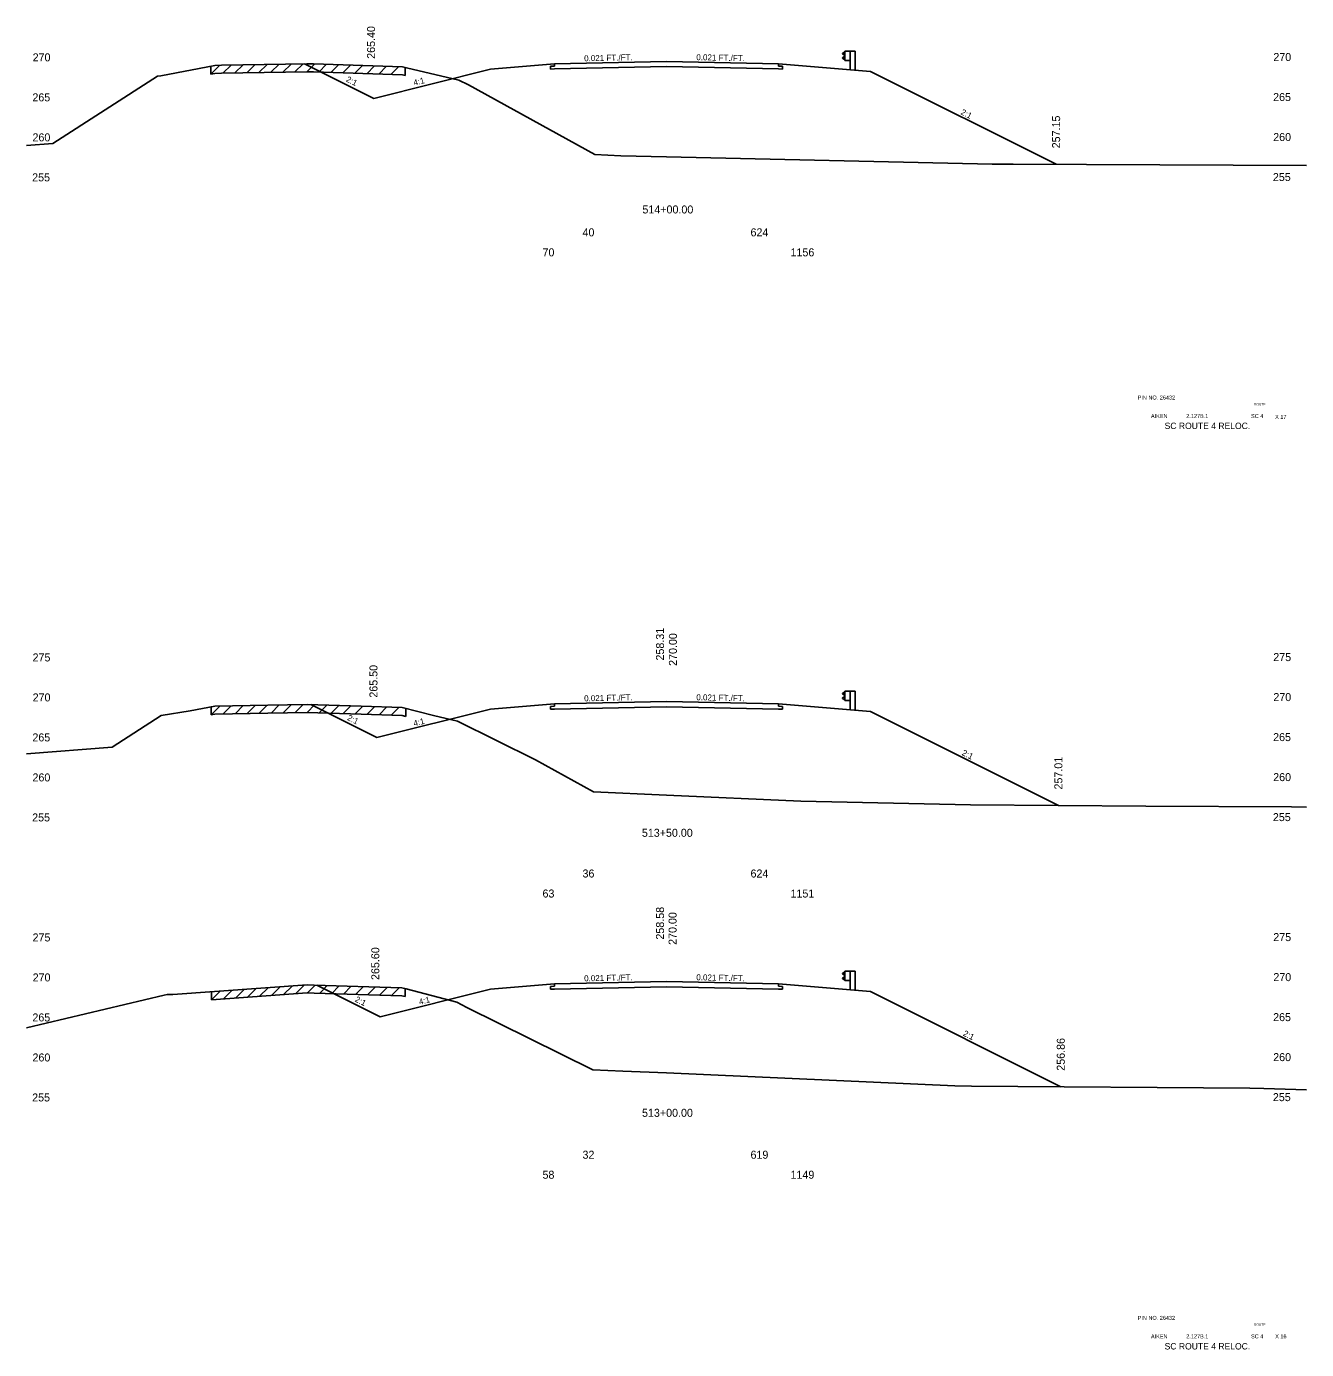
# Model space of a CAD drawing. Extents: x 2967 to 4323, y -3677 to -817.
# Drawn here: x 3188.8 to 3348.8, y -1855.8 to -1690.5 of the extents above; entities that cross this region are included whole.
import ezdxf

# ---------------------------------------------------------------- set-up
doc = ezdxf.new("R2010")
doc.units = 0
for name, color, linetype in [('Level 1', 7, 'Continuous'), ('Level 10', 7, 'Continuous'), ('Level 11', 7, 'Continuous'), ('Level 12', 7, 'Continuous'), ('Level 20', 7, 'Continuous'), ('Level 24', 7, 'Continuous'), ('Level 3', 7, 'Continuous'), ('Level 32', 7, 'Continuous'), ('Level 33', 7, 'Continuous'), ('Level 59', 7, 'Continuous'), ('Level 6', 7, 'Continuous'), ('Level 60', 7, 'Continuous'), ('Level 61', 7, 'Continuous'), ('Level 7', 7, 'Continuous')]:
    doc.layers.add(name, color=color, linetype=linetype)

msp = doc.modelspace()

# ---------------------------------------------------------------- linework, layer by layer
at = {"layer": 'Level 11'}
for p, q in [((3254.76, -1695.43), (3254.26, -1695.44)), ((3254.26, -1695.44), (3254.26, -1695.78)), ((3254.26, -1695.78), (3254.76, -1695.77)), ((3254.76, -1695.13), (3254.76, -1695.43)), ((3282.76, -1695.43), (3282.76, -1695.13)), ((3283.26, -1695.44), (3282.76, -1695.43)), ((3282.76, -1695.77), (3283.26, -1695.78)), ((3283.26, -1695.78), (3283.26, -1695.44)), ((3254.76, -1775.43), (3254.26, -1775.44)), ((3254.26, -1775.44), (3254.26, -1775.78)), ((3254.26, -1775.78), (3254.76, -1775.77)), ((3254.76, -1775.13), (3254.76, -1775.43)), ((3282.76, -1775.43), (3282.76, -1775.13)), ((3283.26, -1775.44), (3282.76, -1775.43)), ((3282.76, -1775.77), (3283.26, -1775.78)), ((3283.26, -1775.78), (3283.26, -1775.44)), ((3254.76, -1810.43), (3254.26, -1810.44)), ((3254.26, -1810.44), (3254.26, -1810.78)), ((3254.26, -1810.78), (3254.76, -1810.77)), ((3254.76, -1810.13), (3254.76, -1810.43)), ((3282.76, -1810.43), (3282.76, -1810.13)), ((3283.26, -1810.44), (3282.76, -1810.43)), ((3282.76, -1810.77), (3283.26, -1810.78)), ((3283.26, -1810.78), (3283.26, -1810.44))]:
    msp.add_line(p, q, dxfattribs=at)
at = {"layer": 'Level 12'}
for p, q in [((3268.76, -1695.48), (3254.76, -1695.77)), ((3282.76, -1695.77), (3268.76, -1695.48)), ((3268.76, -1775.48), (3254.76, -1775.77)), ((3282.76, -1775.77), (3268.76, -1775.48)), ((3268.76, -1810.48), (3254.76, -1810.77)), ((3282.76, -1810.77), (3268.76, -1810.48))]:
    msp.add_line(p, q, dxfattribs=at)
at = {"layer": 'Level 24'}
for p, q in [((3291.03, -1693.62), (3290.76, -1693.82)), ((3290.76, -1693.82), (3290.76, -1693.87)), ((3290.76, -1693.87), (3291.03, -1694.07)), ((3290.76, -1694.39), (3291.03, -1694.19)), ((3290.76, -1694.44), (3290.76, -1694.39)), ((3291.03, -1694.64), (3290.76, -1694.44)), ((3291.03, -1694.72), (3291.03, -1693.55)), ((3291.03, -1693.55), (3291.7, -1693.55)), ((3291.03, -1694.72), (3291.7, -1694.72)), ((3291.7, -1693.55), (3291.7, -1695.88)), ((3291.7, -1693.55), (3292.36, -1693.55)), ((3292.36, -1693.55), (3292.36, -1695.93)), ((3291.03, -1773.62), (3290.76, -1773.82)), ((3290.76, -1773.82), (3290.76, -1773.87)), ((3290.76, -1773.87), (3291.03, -1774.07)), ((3290.76, -1774.39), (3291.03, -1774.19)), ((3290.76, -1774.44), (3290.76, -1774.39)), ((3291.03, -1774.72), (3291.03, -1773.55)), ((3291.03, -1773.55), (3291.7, -1773.55)), ((3291.7, -1773.55), (3291.7, -1775.88)), ((3291.7, -1773.55), (3292.36, -1773.55)), ((3292.36, -1773.55), (3292.36, -1775.93)), ((3291.03, -1774.64), (3290.76, -1774.44)), ((3291.03, -1774.72), (3291.7, -1774.72)), ((3291.03, -1808.62), (3290.76, -1808.82)), ((3290.76, -1808.82), (3290.76, -1808.87)), ((3290.76, -1808.87), (3291.03, -1809.07)), ((3291.03, -1809.72), (3291.03, -1808.55)), ((3291.03, -1808.55), (3291.7, -1808.55)), ((3291.7, -1808.55), (3291.7, -1810.88)), ((3291.7, -1808.55), (3292.36, -1808.55)), ((3292.36, -1808.55), (3292.36, -1810.93)), ((3290.76, -1809.39), (3291.03, -1809.19)), ((3290.76, -1809.44), (3290.76, -1809.39)), ((3291.03, -1809.64), (3290.76, -1809.44)), ((3291.03, -1809.72), (3291.7, -1809.72))]:
    msp.add_line(p, q, dxfattribs=at)
at = {"layer": 'Level 59'}
for p, q in [((3254.76, -1695.13), (3268.76, -1694.84)), ((3268.76, -1694.84), (3282.76, -1695.13)), ((3254.76, -1775.13), (3268.76, -1774.84)), ((3268.76, -1774.84), (3282.76, -1775.13)), ((3254.76, -1810.13), (3268.76, -1809.84)), ((3268.76, -1809.84), (3282.76, -1810.13))]:
    msp.add_line(p, q, dxfattribs=at)
at = {"layer": 'Level 6'}
for p, q in [((3246.76, -1695.8), (3254.76, -1695.13)), ((3282.76, -1695.13), (3290.76, -1695.8)), ((3290.76, -1695.8), (3294.26, -1696.09)), ((3246.76, -1775.8), (3254.76, -1775.13)), ((3282.76, -1775.13), (3290.76, -1775.8)), ((3290.76, -1775.8), (3294.26, -1776.09)), ((3246.76, -1810.8), (3254.76, -1810.13)), ((3282.76, -1810.13), (3290.76, -1810.8)), ((3290.76, -1810.8), (3294.26, -1811.09))]:
    msp.add_line(p, q, dxfattribs=at)
at = {"layer": 'Level 60'}
for p, q in [((3192.07, -1705.07), (3205.12, -1696.68)), ((3205.12, -1696.68), (3205.56, -1696.61)), ((3205.56, -1696.61), (3212.31, -1695.32)), ((3212.31, -1695.32), (3213.13, -1695.3)), ((3213.13, -1695.3), (3223.82, -1695.11)), ((3223.82, -1695.11), (3224.65, -1695.14)), ((3224.65, -1695.14), (3235.77, -1695.5)), ((3235.77, -1695.5), (3236.26, -1695.63)), ((3236.26, -1695.63), (3242.81, -1697.15)), ((3242.81, -1697.15), (3244.03, -1697.76)), ((3244.03, -1697.76), (3259.81, -1706.48)), ((3188.76, -1705.33), (3192.07, -1705.07)), ((3259.81, -1706.48), (3263.03, -1706.62)), ((3263.03, -1706.62), (3268.76, -1706.75)), ((3268.76, -1706.75), (3309.46, -1707.65)), ((3309.46, -1707.65), (3312.1, -1707.67)), ((3312.1, -1707.67), (3348.76, -1707.84)), ((3205.59, -1776.59), (3209.2, -1776.01)), ((3209.2, -1776.01), (3212.32, -1775.41)), ((3212.32, -1775.41), (3218.91, -1775.28)), ((3218.91, -1775.28), (3223.85, -1775.19)), ((3223.85, -1775.19), (3230.59, -1775.4)), ((3230.59, -1775.4), (3235.71, -1775.57)), ((3235.71, -1775.57), (3239.63, -1776.6)), ((3199.46, -1780.53), (3205.59, -1776.59)), ((3239.63, -1776.6), (3242.64, -1777.3)), ((3242.64, -1777.3), (3252.39, -1782.12)), ((3188.76, -1781.36), (3199.46, -1780.53)), ((3252.39, -1782.12), (3259.64, -1786.13)), ((3259.64, -1786.13), (3268.76, -1786.54)), ((3268.76, -1786.54), (3285.56, -1787.28)), ((3285.56, -1787.28), (3306.76, -1787.75)), ((3306.76, -1787.75), (3328.68, -1787.92)), ((3328.68, -1787.92), (3346.87, -1788)), ((3346.87, -1788), (3348.76, -1788.05)), ((3207.04, -1811.44), (3223.86, -1810.26)), ((3223.86, -1810.26), (3224.71, -1810.28)), ((3224.71, -1810.28), (3235.66, -1810.63)), ((3235.66, -1810.63), (3236.23, -1810.73)), ((3236.23, -1810.73), (3242.55, -1812.4)), ((3188.76, -1815.62), (3205.96, -1811.53)), ((3205.96, -1811.53), (3206.36, -1811.46)), ((3206.36, -1811.46), (3207.04, -1811.44)), ((3242.55, -1812.4), (3243.82, -1813.08)), ((3243.82, -1813.08), (3259.55, -1820.85)), ((3259.55, -1820.85), (3263.31, -1821.02)), ((3263.31, -1821.02), (3268.76, -1821.26)), ((3268.76, -1821.26), (3304.8, -1822.86)), ((3304.8, -1822.86), (3306.89, -1822.89)), ((3306.89, -1822.89), (3341.68, -1823.17)), ((3341.68, -1823.17), (3343.43, -1823.21)), ((3343.43, -1823.21), (3348.76, -1823.35))]:
    msp.add_line(p, q, dxfattribs=at)
at = {"layer": 'Level 61'}
for p, q in [((3212.92, -1695.3), (3211.82, -1696.41)), ((3211.82, -1695.41), (3211.82, -1696.41)), ((3211.82, -1696.41), (3212.31, -1696.32)), ((3212.31, -1696.32), (3213.13, -1696.3)), ((3213.13, -1696.3), (3223.82, -1696.11)), ((3214.33, -1695.28), (3213.32, -1696.3)), ((3215.83, -1695.25), (3214.82, -1696.27)), ((3217.33, -1695.23), (3216.32, -1696.24)), ((3218.83, -1695.2), (3217.82, -1696.22)), ((3220.33, -1695.17), (3219.32, -1696.19)), ((3221.83, -1695.15), (3220.82, -1696.17)), ((3223.33, -1695.12), (3222.32, -1696.14)), ((3224.79, -1695.14), (3223.82, -1696.11)), ((3223.82, -1696.11), (3224.65, -1696.14)), ((3224.65, -1696.14), (3235.77, -1696.5)), ((3226.28, -1695.19), (3225.32, -1696.16)), ((3227.78, -1695.24), (3226.82, -1696.21)), ((3229.28, -1695.29), (3228.32, -1696.26)), ((3230.78, -1695.34), (3229.82, -1696.31)), ((3232.28, -1695.39), (3231.32, -1696.36)), ((3233.78, -1695.44), (3232.82, -1696.41)), ((3235.28, -1695.49), (3234.32, -1696.45)), ((3235.77, -1696.5), (3236.09, -1696.59)), ((3236.09, -1696.59), (3236.09, -1695.59)), ((3212.93, -1775.4), (3211.83, -1776.5)), ((3211.83, -1775.5), (3211.83, -1776.5)), ((3214.35, -1775.37), (3213.33, -1776.39)), ((3215.85, -1775.34), (3214.83, -1776.36)), ((3217.35, -1775.31), (3216.33, -1776.33)), ((3218.85, -1775.28), (3217.83, -1776.3)), ((3220.35, -1775.25), (3219.33, -1776.27)), ((3221.85, -1775.23), (3220.83, -1776.25)), ((3223.35, -1775.2), (3222.33, -1776.22)), ((3224.8, -1775.22), (3223.83, -1776.19)), ((3226.3, -1775.27), (3225.33, -1776.24)), ((3227.8, -1775.32), (3226.83, -1776.29)), ((3229.3, -1775.36), (3228.33, -1776.33)), ((3230.8, -1775.41), (3229.83, -1776.38)), ((3232.3, -1775.46), (3231.33, -1776.43)), ((3233.8, -1775.51), (3232.83, -1776.48)), ((3235.3, -1775.56), (3234.33, -1776.53)), ((3236.17, -1776.69), (3236.17, -1775.69)), ((3211.83, -1776.5), (3212.32, -1776.41)), ((3212.32, -1776.41), (3218.91, -1776.28)), ((3218.91, -1776.28), (3223.85, -1776.19)), ((3223.85, -1776.19), (3230.59, -1776.4)), ((3230.59, -1776.4), (3235.71, -1776.57)), ((3235.71, -1776.57), (3236.17, -1776.69)), ((3217.46, -1810.71), (3216.39, -1811.79)), ((3218.96, -1810.6), (3217.89, -1811.68)), ((3220.46, -1810.5), (3219.39, -1811.58)), ((3221.96, -1810.39), (3220.89, -1811.47)), ((3223.46, -1810.29), (3222.39, -1811.37)), ((3224.86, -1810.29), (3223.89, -1811.26)), ((3226.36, -1810.34), (3225.39, -1811.31)), ((3227.86, -1810.38), (3226.89, -1811.35)), ((3229.36, -1810.43), (3228.39, -1811.4)), ((3230.86, -1810.48), (3229.89, -1811.45)), ((3232.36, -1810.52), (3231.39, -1811.49)), ((3233.86, -1810.57), (3232.89, -1811.54)), ((3235.36, -1810.62), (3234.39, -1811.59)), ((3236.11, -1811.71), (3236.11, -1810.71)), ((3212.96, -1811.02), (3211.89, -1812.1)), ((3211.89, -1811.1), (3211.89, -1812.1)), ((3211.89, -1812.1), (3223.86, -1811.26)), ((3214.46, -1810.92), (3213.39, -1812)), ((3215.96, -1810.81), (3214.89, -1811.89)), ((3223.86, -1811.26), (3224.71, -1811.28)), ((3224.71, -1811.28), (3235.66, -1811.63)), ((3235.66, -1811.63), (3236.11, -1811.71))]:
    msp.add_line(p, q, dxfattribs=at)
at = {"layer": 'Level 7'}
for p, q in [((3223.52, -1695.12), (3232.17, -1699.45)), ((3246.76, -1695.8), (3232.17, -1699.45)), ((3294.26, -1696.09), (3317.46, -1707.69)), ((3224.29, -1775.21), (3232.57, -1779.35)), ((3246.76, -1775.8), (3232.57, -1779.35)), ((3294.26, -1776.09), (3317.74, -1787.83)), ((3225.07, -1810.3), (3232.97, -1814.25)), ((3246.76, -1810.8), (3232.97, -1814.25)), ((3294.26, -1811.09), (3318.04, -1822.98))]:
    msp.add_line(p, q, dxfattribs=at)

# ---------------------------------------------------------------- texts
at = {"layer": 'Level 1'}
for s, p in [('40', (3258.26, -1716.69)), ('624', (3279.26, -1716.69)), ('70', (3253.26, -1719.19)), ('1156', (3284.26, -1719.19)), ('36', (3258.26, -1796.83)), ('624', (3279.26, -1796.83)), ('63', (3253.26, -1799.33)), ('1151', (3284.26, -1799.33)), ('32', (3258.26, -1831.98)), ('619', (3279.26, -1831.98)), ('58', (3253.26, -1834.48)), ('1149', (3284.26, -1834.48))]:
    msp.add_text(s, height=1, dxfattribs=at).set_placement(p)
at = {"layer": 'Level 10'}
for s, p in [('514+00.00', (3265.75, -1713.83)), ('513+50.00', (3265.68, -1791.74)), ('513+00.00', (3265.7, -1826.74))]:
    msp.add_text(s, height=1, dxfattribs=at).set_placement(p)
for s, p in [('258.31', (3268.45, -1769.71)), ('258.58', (3268.45, -1804.59))]:
    msp.add_text(s, height=1, rotation=90, dxfattribs=at).set_placement(p)
at = {"layer": 'Level 20'}
for s, height, p in [('PIN NO. 26432', 0.5, (3327.65, -1737.09)), ('ROUTE', 0.3, (3342.19, -1737.83)), ('AIKEN', 0.5, (3329.31, -1739.4)), (' 2.127B.1', 0.5, (3333.53, -1739.4)), ('SC 4', 0.5, (3341.82, -1739.4)), ('X 17', 0.5, (3344.83, -1739.5)), ('SC ROUTE 4 RELOC.', 0.8, (3331.02, -1740.78)), ('PIN NO. 26432', 0.5, (3327.65, -1852.12)), ('ROUTE', 0.3, (3342.19, -1852.86)), ('AIKEN', 0.5, (3329.31, -1854.43)), ('SC ROUTE 4 RELOC.', 0.8, (3331.02, -1855.82)), (' 2.127B.1', 0.5, (3333.53, -1854.43)), ('SC 4', 0.5, (3341.82, -1854.43)), ('X 16', 0.5, (3344.84, -1854.43))]:
    msp.add_text(s, height=height, dxfattribs=at).set_placement(p)
at = {"layer": 'Level 3'}
for s, p in [(' 270', (3189.16, -1694.82)), (' 270', (3344.24, -1694.78)), (' 265', (3189.13, -1699.82)), (' 265', (3344.21, -1699.78)), (' 260', (3189.14, -1704.82)), (' 260', (3344.22, -1704.78)), (' 255', (3189.1, -1709.82)), (' 255', (3344.18, -1709.78)), (' 275', (3189.15, -1769.82)), (' 275', (3344.23, -1769.78)), (' 270', (3189.16, -1774.82)), (' 270', (3344.24, -1774.78)), (' 265', (3189.13, -1779.82)), (' 265', (3344.21, -1779.78)), (' 260', (3189.14, -1784.82)), (' 260', (3344.22, -1784.78)), (' 255', (3189.1, -1789.82)), (' 255', (3344.18, -1789.78)), (' 275', (3189.15, -1804.82)), (' 275', (3344.23, -1804.78)), (' 270', (3189.16, -1809.82)), (' 270', (3344.24, -1809.78)), (' 265', (3189.13, -1814.82)), (' 265', (3344.21, -1814.78)), (' 260', (3189.14, -1819.82)), (' 260', (3344.22, -1819.78)), (' 255', (3189.1, -1824.82)), (' 255', (3344.18, -1824.78))]:
    msp.add_text(s, height=1, dxfattribs=at).set_placement(p)
at = {"layer": 'Level 32'}
for s, rotation, p in [('0.021 FT./FT.', 1.1916, (3258.47, -1694.81)), ('0.021 FT./FT.', 358.8084, (3272.48, -1694.67)), ('2:1', 333.435, (3228.63, -1697.3)), ('4:1', 14.0362, (3237.23, -1697.87)), ('2:1', 333.435, (3305.46, -1701.41)), ('0.021 FT./FT.', 1.1916, (3258.47, -1774.81)), ('0.021 FT./FT.', 358.8084, (3272.48, -1774.67)), ('2:1', 333.435, (3228.78, -1777.11)), ('4:1', 14.0362, (3237.23, -1777.95)), ('2:1', 333.435, (3305.61, -1781.49)), ('0.021 FT./FT.', 1.1916, (3258.47, -1809.81)), ('0.021 FT./FT.', 358.8084, (3272.48, -1809.67)), ('2:1', 333.435, (3229.74, -1812.3)), ('4:1', 14.0362, (3237.91, -1812.75)), ('2:1', 333.435, (3305.75, -1816.56))]:
    msp.add_text(s, height=0.75, rotation=rotation, dxfattribs=at).set_placement(p)
at = {"layer": 'Level 33'}
for s, p in [('265.40', (3232.33, -1694.5)), ('257.15', (3317.96, -1705.69)), ('265.50', (3232.63, -1774.35)), ('257.01', (3318.24, -1785.83)), ('265.60', (3232.86, -1809.64)), ('256.86', (3318.54, -1820.98))]:
    msp.add_text(s, height=1, rotation=90, dxfattribs=at).set_placement(p)
at = {"layer": 'Level 59'}
for p in [(3270.06, -1770.75), (3270.02, -1805.62)]:
    msp.add_text(' 270.00', height=1, rotation=90, dxfattribs=at).set_placement(p)

doc.saveas('drawing.dxf')
